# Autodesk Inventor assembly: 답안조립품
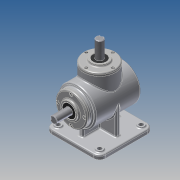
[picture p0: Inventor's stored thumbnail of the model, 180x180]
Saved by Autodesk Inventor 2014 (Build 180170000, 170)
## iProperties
Created: 2015-07
Part Number: 답안조립품
Document SubType Name: Assembly
Designer: user
Author: user
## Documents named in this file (14)
- C:\Users\user\Desktop\답안조립품.iam
- C:\Users\user\Desktop\본체.ipt
- C:\Users\user\Desktop\450706V1009\M4.ipt
- C:\Users\user\Desktop\450706V1009\메인 베벨기어.ipt
- C:\Users\user\Desktop\450706V1009\메인 축.ipt
- 메인 축.ipt
- C:\Users\user\Desktop\450706V1009\베어링 6203.ipt
- C:\Users\user\Desktop\450706V1009\서브 베벨기어.ipt
- C:\Users\user\Desktop\450706V1009\서브 축.ipt
- 서브 축.ipt
- C:\Users\user\Desktop\450706V1009\오일실.ipt
- C:\Users\user\Desktop\450706V1009\커버.ipt
- C:\Users\user\Desktop\450706V1009\키 4x4.ipt
- C:\Users\user\Desktop\450706V1009\키 5x5.ipt
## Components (8 placed, 1 different names)
1. M4:1 — Mate:25, Mate:26
2. M4:3
3. M4:4
4. M4:5
5. M4:2 — Mate:27, Mate:28
6. M4:6
7. M4:7
8. M4:8
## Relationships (4: Mate 4)
- Mate:25: M4:1
- Mate:26: M4:1
- Mate:27: M4:2
- Mate:28: M4:2
